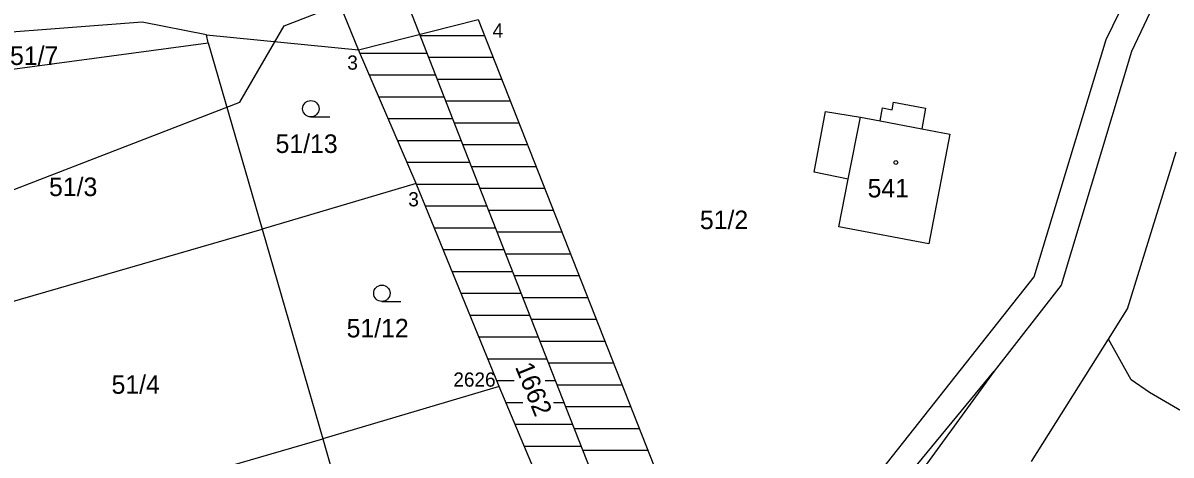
# Model space of a CAD drawing. Extents: x -553916 to -552953, y -1067469 to -1066637.
# Drawn here: x -553578.9 to -553473.7, y -1066946.9 to -1066907.3 of the extents above; entities that cross this region are included whole.
import ezdxf

# ---------------------------------------------------------------- set-up
doc = ezdxf.new("R2010")
doc.units = 0
for name, color, linetype in [('Hranice parcel', 7, 'Continuous'), ('Kolej', 7, 'Continuous'), ('Parcelní čísla', 7, 'Continuous'), ('Přejezd - štěrkové lože', 7, 'Continuous'), ('Vnitřní kresba', 7, 'Continuous'), ('Vrstva 1', 7, 'Continuous'), ('Vrstva 60', 7, 'Continuous'), ('Značky budov', 7, 'Continuous'), ('Značky kultur', 7, 'Continuous')]:
    doc.layers.add(name, color=color, linetype=linetype)

msp = doc.modelspace()

# ---------------------------------------------------------------- linework, layer by layer
at = {"layer": 'Hranice parcel'}
for p, q in [((-553562.08, -1066908.37), (-553548.13, -1066909.75)), ((-553561.91, -1066909.12), (-553562.08, -1066908.37)), ((-553591.97, -1066913.14), (-553561.91, -1066909.12)), ((-553561.91, -1066909.12), (-553556.97, -1066926.17)), ((-553542.85, -1066922.01), (-553556.97, -1066926.17)), ((-553585.78, -1066934.51), (-553556.97, -1066926.17)), ((-553556.97, -1066926.17), (-553551.41, -1066945.38)), ((-553486.47, -1066947.45), (-553479.42, -1066936.25)), ((-553514.13, -1066968.51), (-553489.9, -1066939.2)), ((-553535.26, -1066940.6), (-553551.41, -1066945.38)), ((-553580.22, -1066953.72), (-553551.41, -1066945.38)), ((-553551.41, -1066945.38), (-553545.85, -1066964.59))]:
    msp.add_line(p, q, dxfattribs=at)
for points in [[(-553468.58, -1066891.47), (-553477.31, -1066909.92), (-553483.75, -1066931.3), (-553489.9, -1066939.2)], [(-553515.05, -1066965.6), (-553502.53, -1066951.2), (-553486.22, -1066930.56), (-553479.63, -1066908.8), (-553477.16, -1066903.7)], [(-553562.08, -1066908.37), (-553567.96, -1066907.21), (-553588.75, -1066908.8), (-553591.81, -1066911.32)], [(-553495.88, -1066927.52), (-553504.13, -1066925.96), (-553503.27, -1066921.61), (-553506.38, -1066920.95), (-553505.35, -1066915.4), (-553502.13, -1066915.91), (-553500.34, -1066916.26), (-553500.12, -1066915.07), (-553499.24, -1066915.24), (-553499.11, -1066914.55), (-553496.17, -1066915.11), (-553496.51, -1066917), (-553493.96, -1066917.49), (-553495.88, -1066927.52)], [(-553479.42, -1066936.25), (-553477.68, -1066933.49), (-553473.2, -1066919.09)], [(-553444.09, -1066959.55), (-553475.65, -1066941.14), (-553477.33, -1066939.99), (-553479.42, -1066936.25)], [(-553489.9, -1066939.2), (-553506.21, -1066961.59), (-553507.62, -1066963.64), (-553510.49, -1066967.37), (-553513.35, -1066970.96)]]:
    msp.add_lwpolyline(points, dxfattribs=at)
at = {"layer": 'Kolej'}
msp.add_lwpolyline([(-553503.32, -1067065.81), (-553502.68, -1067054.03), (-553502.76, -1067041.5), (-553503.63, -1067029.06), (-553504.76, -1067019.97), (-553506.18, -1067011.39), (-553508.33, -1067001.39), (-553510.95, -1066991.62), (-553512.92, -1066985.29), (-553515.65, -1066977.35), (-553517.42, -1066972.53), (-553519.16, -1066967.95), (-553522.89, -1066958.38), (-553529.1, -1066942.55), (-553538.69, -1066918.11), (-553542.91, -1066907.33), (-553546.69, -1066897.68), (-553555.03, -1066876.44), (-553564.64, -1066851.89), (-553574.24, -1066827.43), (-553583.19, -1066804.62)], dxfattribs=at)
at = {"layer": 'Přejezd - štěrkové lože'}
msp.add_lwpolyline([(-553598.54, -1066929.82), (-553559.03, -1066914.56), (-553554.95, -1066907.55), (-553544.41, -1066903.46)], dxfattribs=at)
at = {"layer": 'Vnitřní kresba'}
for p, q in [((-553503.27, -1066921.61), (-553502.13, -1066915.91)), ((-553500.34, -1066916.26), (-553496.51, -1066917))]:
    msp.add_line(p, q, dxfattribs=at)
at = {"layer": 'Vrstva 1'}
for p, q in [((-553548.13, -1066909.75), (-553550.91, -1066902.91)), ((-553548.13, -1066909.75), (-553537.18, -1066906.98)), ((-553542.48, -1066908.43), (-553536.61, -1066908.43)), ((-553542.85, -1066922.01), (-553548.13, -1066909.75)), ((-553548, -1066910.05), (-553541.84, -1066910.05)), ((-553541.69, -1066910.43), (-553535.82, -1066910.43)), ((-553547.14, -1066912.05), (-553541.06, -1066912.05)), ((-553540.91, -1066912.43), (-553535.03, -1066912.43)), ((-553546.28, -1066914.05), (-553540.27, -1066914.05)), ((-553540.13, -1066914.43), (-553534.25, -1066914.43)), ((-553545.42, -1066916.05), (-553539.49, -1066916.05)), ((-553539.34, -1066916.43), (-553533.46, -1066916.43)), ((-553544.55, -1066918.05), (-553538.71, -1066918.05)), ((-553538.56, -1066918.43), (-553532.67, -1066918.43)), ((-553543.69, -1066920.05), (-553537.92, -1066920.05)), ((-553537.78, -1066920.43), (-553531.88, -1066920.43)), ((-553535.26, -1066940.6), (-553542.85, -1066922.01)), ((-553542.83, -1066922.05), (-553537.14, -1066922.05)), ((-553536.99, -1066922.43), (-553531.09, -1066922.43)), ((-553542.02, -1066924.05), (-553536.35, -1066924.05)), ((-553536.21, -1066924.43), (-553530.31, -1066924.43)), ((-553541.2, -1066926.05), (-553535.57, -1066926.05)), ((-553535.42, -1066926.43), (-553529.52, -1066926.43)), ((-553540.38, -1066928.05), (-553534.79, -1066928.05)), ((-553534.64, -1066928.43), (-553528.73, -1066928.43)), ((-553539.57, -1066930.05), (-553534, -1066930.05)), ((-553533.85, -1066930.43), (-553527.94, -1066930.43)), ((-553538.75, -1066932.05), (-553533.22, -1066932.05)), ((-553533.07, -1066932.43), (-553527.16, -1066932.43)), ((-553537.93, -1066934.05), (-553532.43, -1066934.05)), ((-553532.29, -1066934.43), (-553526.37, -1066934.43)), ((-553537.12, -1066936.05), (-553531.65, -1066936.05)), ((-553531.5, -1066936.43), (-553525.58, -1066936.43)), ((-553536.3, -1066938.05), (-553530.86, -1066938.05)), ((-553530.72, -1066938.43), (-553524.79, -1066938.43)), ((-553535.48, -1066940.05), (-553533.88, -1066940.05)), ((-553531.04, -1066940.05), (-553530.08, -1066940.05)), ((-553527.43, -1066959.15), (-553535.26, -1066940.6)), ((-553529.93, -1066940.43), (-553524, -1066940.43)), ((-553534.65, -1066942.05), (-553533.09, -1066942.05)), ((-553530.27, -1066942.05), (-553529.3, -1066942.05)), ((-553529.15, -1066942.43), (-553523.22, -1066942.43)), ((-553533.8, -1066944.05), (-553528.51, -1066944.05)), ((-553528.36, -1066944.43), (-553522.43, -1066944.43)), ((-553532.96, -1066946.05), (-553527.73, -1066946.05)), ((-553527.58, -1066946.43), (-553521.64, -1066946.43))]:
    msp.add_line(p, q, dxfattribs=at)
msp.add_lwpolyline([(-553537.18, -1066906.98), (-553519.04, -1066953.03), (-553515.05, -1066965.6)], dxfattribs=at)
at = {"layer": 'Vrstva 60'}
for p, q in [((-553548.13, -1066909.75), (-553548.13, -1066909.75)), ((-553542.85, -1066922.01), (-553542.85, -1066922.01)), ((-553535.26, -1066940.6), (-553535.26, -1066940.6))]:
    msp.add_line(p, q, dxfattribs=at)
at = {"layer": 'Značky budov'}
msp.add_circle((-553498.9, -1066920.07), 0.175, dxfattribs=at)
at = {"layer": 'Značky kultur'}
for p, q in [((-553552.51, -1066915.9), (-553550.76, -1066915.9)), ((-553546, -1066932.8), (-553544.25, -1066932.8))]:
    msp.add_line(p, q, dxfattribs=at)
for centre in [(-553552.51, -1066915.15), (-553546, -1066932.05)]:
    msp.add_circle(centre, 0.75, dxfattribs=at)

# ---------------------------------------------------------------- texts
at = {"layer": 'Parcelní čísla'}
for s, p in [('51/7', (-553580.07, -1066911.14)), ('51/13', (-553555.74, -1066919.2)), ('51/3', (-553576.5, -1066923.15)), ('541', (-553501.49, -1066923.27)), ('51/2', (-553516.86, -1066926.18)), ('51/12', (-553549.23, -1066936.1)), ('51/4', (-553570.77, -1066941.26))]:
    msp.add_text(s, height=1.7, dxfattribs=at).set_placement(p)
at = {"layer": 'Vrstva 1'}
msp.add_text('1662', height=1.7, rotation=292, dxfattribs=at).set_placement((-553533.82, -1066938.79))
at = {"layer": 'Vrstva 60'}
for s, p in [('4', (-553535.85, -1066908.63)), ('3', (-553549.17, -1066911.57)), ('3', (-553543.58, -1066924.09)), ('2626', (-553539.45, -1066940.61))]:
    msp.add_text(s, height=1.3, dxfattribs=at).set_placement(p)

doc.saveas('drawing.dxf')
